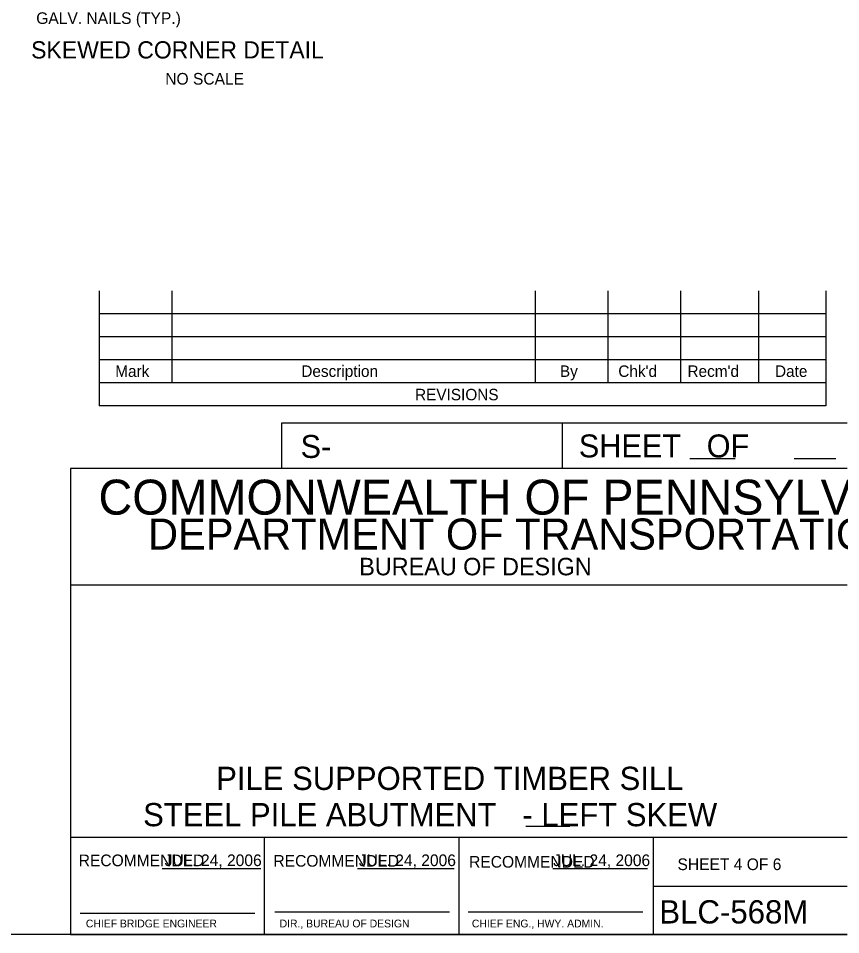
# Model space of a CAD drawing. Extents: x 635440 to 640306, y 296653 to 298484.
# Drawn here: x 639889.1 to 640100.8, y 297856.5 to 298092.3 of the extents above; entities that cross this region are included whole.
import ezdxf

# ---------------------------------------------------------------- set-up
doc = ezdxf.new("R2010")
doc.units = 0
for name, color, linetype in [('2', 7, 'Continuous'), ('4', 7, 'Continuous'), ('5', 7, 'Continuous')]:
    doc.layers.add(name, color=color, linetype=linetype)

msp = doc.modelspace()

# ---------------------------------------------------------------- linework, layer by layer
at = {"layer": '2'}
for p, q in [((639909.92, 298022.15), (639909.92, 297992.62)), ((639928.62, 298022.15), (639928.62, 297998.53)), ((640022.13, 298022.15), (640022.13, 297998.53)), ((640040.83, 298022.15), (640040.83, 297998.53)), ((640059.53, 298022.15), (640059.53, 297998.53)), ((640079.59, 298022.15), (640079.59, 297998.53)), ((640096.94, 298022.15), (640096.94, 297992.62)), ((640096.94, 298016.24), (639909.92, 298016.24)), ((640096.94, 298010.34), (639909.92, 298010.34)), ((640096.94, 298004.43), (639909.92, 298004.43)), ((640096.94, 297998.53), (639909.92, 297998.53)), ((640096.94, 297992.62), (639909.92, 297992.62)), ((640102.46, 297988.11), (639956.78, 297988.11)), ((639956.78, 297988.11), (639956.78, 297976.46)), ((640029.09, 297988.11), (640029.09, 297976.46)), ((640061.95, 297979), (640073.6, 297979)), ((640088.83, 297979), (640099.56, 297979)), ((640102.46, 297976.46), (639902.46, 297976.46)), ((639902.46, 297976.46), (639902.46, 297856.46)), ((640102.46, 297946.46), (639902.46, 297946.46)), ((640102.46, 297881.46), (639902.46, 297881.46)), ((639952.46, 297856.46), (639952.46, 297881.46)), ((640002.46, 297881.46), (640002.46, 297856.46)), ((640052.46, 297881.46), (640052.46, 297856.46)), ((639926.11, 297873.46), (639951.49, 297873.46)), ((639976.38, 297873.46), (640001.27, 297873.46)), ((640026.65, 297873.46), (640051.06, 297873.46)), ((640052.46, 297868.96), (640102.46, 297868.96)), ((639904.96, 297861.96), (639949.96, 297861.96)), ((639955.08, 297862.33), (640000.08, 297862.33)), ((640004.83, 297862.33), (640049.83, 297862.33)), ((640102.46, 297856.46), (639316.46, 297856.46)), ((639902.46, 297856.46), (640102.46, 297856.46))]:
    msp.add_line(p, q, dxfattribs=at)
at = {"layer": '4'}
msp.add_line((640019.69, 297884.41), (640031.05, 297884.41), dxfattribs=at)

# ---------------------------------------------------------------- texts
at = {"layer": '2'}
for s, height, p in [('Mark', 2.952, (639914.02, 298000.03)), ('Description', 2.9523, (639961.92, 298000.03)), ('By', 2.952, (640028.49, 298000.03)), ("Chk'd", 2.952, (640043.52, 298000.03)), ("Recm'd", 2.953, (640061.33, 298000.03)), ('Date', 2.952, (640083.86, 298000.03)), ('REVISIONS', 2.952, (639991.2, 297994.01)), ('S-', 5.905, (639961.73, 297979.17)), ('COMMONWEALTH OF PENNSYLVANIA', 9, (639909.71, 297964.58)), ('DEPARTMENT OF TRANSPORTATION', 8.0002, (639922.46, 297955.58)), ('BUREAU OF DESIGN', 4.5, (639976.83, 297948.96)), ('STEEL PILE ABUTMENT   - LEFT SKEW', 5.9728, (639921.19, 297884.37)), ('RECOMMENDED', 3, (639904.61, 297874.08)), ('JUL. 24, 2006', 3, (639926.74, 297874.11)), ('RECOMMENDED', 3, (639954.74, 297873.96)), ('JUL. 24, 2006', 3, (639976.74, 297874.11)), ('JUL. 24, 2006', 3, (640026.74, 297874.11)), ('RECOMMENDED', 3, (640005.11, 297873.71)), ('SHEET 4 OF 6', 3, (640058.75, 297873.08)), ('BLC-568M', 6, (640054.08, 297859.33)), ('CHIEF BRIDGE ENGINEER', 2.0002, (639906.46, 297858.33)), ('DIR., BUREAU OF DESIGN', 2.0002, (639956.33, 297858.33)), ('CHIEF ENG., HWY. ADMIN.', 2.0002, (640005.83, 297858.33))]:
    msp.add_text(s, height=height, dxfattribs=at).set_placement(p)
msp.add_text('SHEET   OF', height=5.907, rotation=360, dxfattribs=at).set_placement((640033.35, 297979.31))
at = {"layer": '4'}
for s, height, p in [('SKEWED CORNER DETAIL', 4.4294, (639892.36, 298082)), ('NO SCALE', 3, (639926.89, 298075.27)), ('PILE SUPPORTED TIMBER SILL', 5.9728, (639940.01, 297893.71))]:
    msp.add_text(s, height=height, dxfattribs=at).set_placement(p)
at = {"layer": '5'}
msp.add_text('GALV. NAILS (TYP.)', height=3.0001, dxfattribs=at).set_placement((639893.68, 298090.88))

doc.saveas('drawing.dxf')
